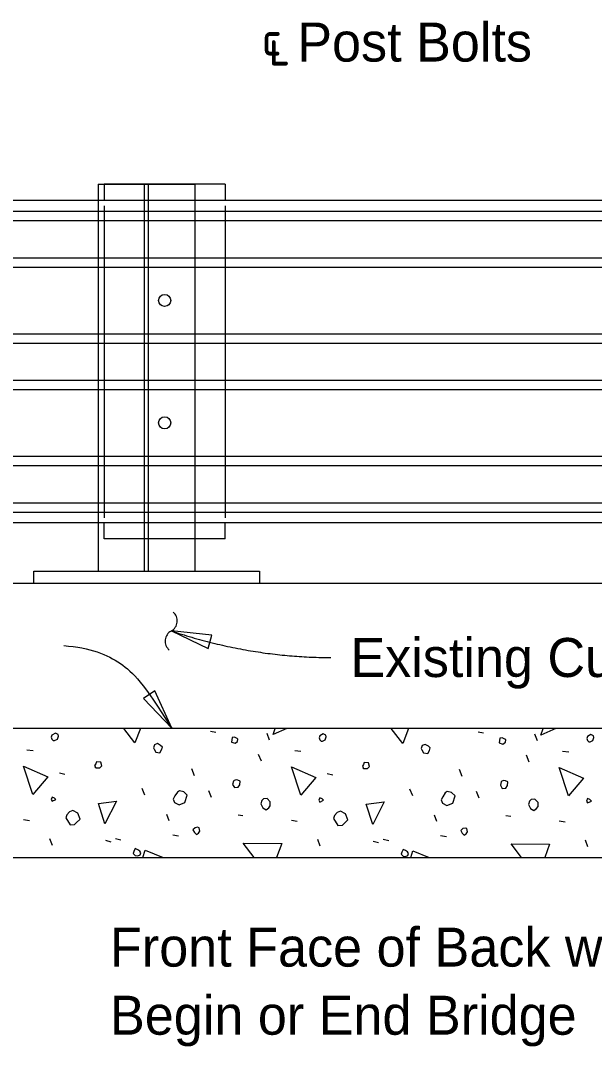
# Model space of a CAD drawing. Extents: x 21665 to 21741.5, y 56121.9 to 56164.2.
# Drawn here: x 21679.75 to 21682.72, y 56140.02 to 56145.33 of the extents above; entities that cross this region are included whole.
import ezdxf

# ---------------------------------------------------------------- set-up
doc = ezdxf.new("R2010")
doc.units = 0
for name, color, linetype in [('Dimension', 7, 'Continuous'), ('ExistSuperStruct', 7, 'Continuous'), ('Miscellaneous', 7, 'Continuous'), ('SteelMisc', 7, 'Continuous'), ('SteelMisc_h', 7, 'Continuous'), ('TextStructures', 7, 'Continuous')]:
    doc.layers.add(name, color=color, linetype=linetype)

msp = doc.modelspace()

# ---------------------------------------------------------------- linework, layer by layer
at = {"layer": 'Dimension'}
for points in [[(21680.5288, 56142.1727), (21680.7195, 56142.0819), (21680.7388, 56142.1497)], [(21680.5306, 56141.6698), (21680.4441, 56141.8625), (21680.3855, 56141.8233)]]:
    msp.add_lwpolyline(points, close=True, dxfattribs=at)
for centre, start, end in [((21680.4996, 56142.2244), 298.3371, 50.0643), ((21680.5562, 56142.1195), 118.3371, 230.0643)]:
    msp.add_arc(centre, 0.0596, start, end, dxfattribs=at)
for points, degree in [([(21680.528, 56142.1727), (21680.9408, 56142.035), (21681.3536, 56142.035)], 2), ([(21679.972, 56142.0966), (21680.1099, 56142.087), (21680.284, 56142.0123), (21680.3829, 56141.9034), (21680.5306, 56141.6698)], 3)]:
    msp.add_open_spline(points, degree=degree, dxfattribs=at)
at = {"layer": 'ExistSuperStruct'}
for p, q in [((21674.8449, 56142.4186), (21684.442, 56142.4186)), ((21684.5591, 56141.6686), (21674.8449, 56141.6686)), ((21674.8449, 56141.0019), (21684.5591, 56141.0019))]:
    msp.add_line(p, q, dxfattribs=at)
at = {"layer": 'Miscellaneous'}
for p, q in [((21680.8066, 56144.4811), (21680.1816, 56144.4811)), ((21680.1816, 56144.4811), (21680.1816, 56144.3977)), ((21680.8066, 56144.4811), (21680.8066, 56144.3977)), ((21680.1816, 56144.3692), (21680.1816, 56142.7573)), ((21680.8066, 56144.3692), (21680.8066, 56142.7573)), ((21680.1816, 56142.6477), (21680.1816, 56142.7311)), ((21680.8066, 56142.6477), (21680.8066, 56142.7311)), ((21680.8066, 56142.6477), (21680.1816, 56142.6477)), ((21680.7314, 56141.655), (21680.7579, 56141.6497)), ((21681.0366, 56141.6079), (21681.0242, 56141.6415)), ((21682.116, 56141.6515), (21682.1425, 56141.6462)), ((21682.4212, 56141.6044), (21682.4089, 56141.6379)), ((21679.7821, 56141.5578), (21679.8139, 56141.5542)), ((21680.9941, 56141.4983), (21680.98, 56141.5336)), ((21681.1667, 56141.5542), (21681.1986, 56141.5507)), ((21682.3788, 56141.4948), (21682.3647, 56141.5301)), ((21682.5514, 56141.5507), (21682.5832, 56141.5472)), ((21680.6483, 56141.4234), (21680.6341, 56141.4588)), ((21682.0329, 56141.4199), (21682.0188, 56141.4552)), ((21679.95, 56141.4393), (21679.9783, 56141.4323)), ((21681.3347, 56141.4358), (21681.363, 56141.4287)), ((21680.3919, 56141.3227), (21680.3778, 56141.358)), ((21681.7766, 56141.3191), (21681.7625, 56141.3545)), ((21680.736, 56141.3109), (21680.7219, 56141.3463)), ((21682.1207, 56141.3074), (21682.1066, 56141.3427)), ((21679.765, 56141.1978), (21679.7951, 56141.1925)), ((21680.5175, 56141.1901), (21680.5051, 56141.2237)), ((21680.8739, 56141.2225), (21680.8987, 56141.219)), ((21681.1497, 56141.1942), (21681.1797, 56141.1889)), ((21681.9021, 56141.1865), (21681.8898, 56141.2201)), ((21682.2586, 56141.219), (21682.2833, 56141.2154)), ((21682.5344, 56141.1907), (21682.5644, 56141.1854)), ((21679.9135, 56141.0634), (21679.9011, 56141.097)), ((21680.1875, 56141.0899), (21680.2158, 56141.0829)), ((21680.2399, 56141.0999), (21680.2682, 56141.0928)), ((21680.5363, 56141.1182), (21680.5663, 56141.1129)), ((21681.2982, 56141.0599), (21681.2858, 56141.0935)), ((21681.5722, 56141.0864), (21681.6005, 56141.0793)), ((21681.6246, 56141.0964), (21681.6529, 56141.0893)), ((21681.921, 56141.1147), (21681.951, 56141.1094)), ((21682.6829, 56141.0563), (21682.6705, 56141.0899))]:
    msp.add_line(p, q, dxfattribs=at)
for points in [[(21680.3407, 56141.5931), (21680.2833, 56141.6686)], [(21680.3689, 56141.6686), (21680.3407, 56141.5931)], [(21681.0554, 56141.6373), (21681.065, 56141.6686)], [(21681.125, 56141.6686), (21681.0554, 56141.6373)], [(21681.7254, 56141.5896), (21681.6653, 56141.6686)], [(21681.7549, 56141.6686), (21681.7254, 56141.5896)], [(21682.44, 56141.6338), (21682.4508, 56141.6686)], [(21682.5175, 56141.6686), (21682.44, 56141.6338)], [(21679.9182, 56141.6055), (21679.9253, 56141.6055), (21679.9394, 56141.6126), (21679.9447, 56141.6285), (21679.9429, 56141.6373), (21679.9288, 56141.6444), (21679.9111, 56141.6338), (21679.9076, 56141.6232), (21679.9111, 56141.6126), (21679.9182, 56141.6055)], [(21680.8392, 56141.5967), (21680.8586, 56141.5914), (21680.871, 56141.6002), (21680.8728, 56141.6126), (21680.8692, 56141.6161), (21680.8551, 56141.6232), (21680.8427, 56141.6214), (21680.841, 56141.609), (21680.8392, 56141.5967)], [(21681.3029, 56141.602), (21681.3099, 56141.602), (21681.3241, 56141.609), (21681.3294, 56141.6249), (21681.3276, 56141.6338), (21681.3135, 56141.6409), (21681.2958, 56141.6302), (21681.2923, 56141.6196), (21681.2958, 56141.609), (21681.3029, 56141.602)], [(21682.2239, 56141.5931), (21682.2433, 56141.5878), (21682.2557, 56141.5967), (21682.2575, 56141.609), (21682.2539, 56141.6126), (21682.2398, 56141.6196), (21682.2274, 56141.6179), (21682.2256, 56141.6055), (21682.2239, 56141.5931)], [(21682.6875, 56141.5984), (21682.6946, 56141.5984), (21682.7087, 56141.6055), (21682.7141, 56141.6214), (21682.7123, 56141.6302), (21682.6981, 56141.6373), (21682.6805, 56141.6267), (21682.6769, 56141.6161), (21682.6805, 56141.6055), (21682.6875, 56141.5984)], [(21680.4397, 56141.5613), (21680.4485, 56141.5454), (21680.4697, 56141.5419), (21680.4786, 56141.5578), (21680.4821, 56141.5719), (21680.4733, 56141.5807), (21680.4574, 56141.5896), (21680.4414, 56141.5843), (21680.4361, 56141.5684), (21680.4397, 56141.5613)], [(21681.8244, 56141.5578), (21681.8332, 56141.5419), (21681.8544, 56141.5383), (21681.8632, 56141.5542), (21681.8668, 56141.5684), (21681.8579, 56141.5772), (21681.842, 56141.5861), (21681.8261, 56141.5807), (21681.8208, 56141.5648), (21681.8244, 56141.5578)], [(21679.8127, 56141.3268), (21679.765, 56141.4735), (21679.8905, 56141.4187), (21679.8127, 56141.3268)], [(21680.1374, 56141.4641), (21680.1586, 56141.4641), (21680.1692, 56141.4747), (21680.1639, 56141.4941), (21680.1409, 56141.4959), (21680.1374, 56141.4853), (21680.1321, 56141.4764), (21680.1374, 56141.4641), (21680.1338, 56141.4676)], [(21681.1974, 56141.3233), (21681.1497, 56141.47), (21681.2752, 56141.4152), (21681.1974, 56141.3233)], [(21681.5221, 56141.4605), (21681.5433, 56141.4605), (21681.5539, 56141.4711), (21681.5486, 56141.4906), (21681.5256, 56141.4924), (21681.5221, 56141.4818), (21681.5168, 56141.4729), (21681.5221, 56141.4605), (21681.5185, 56141.4641)], [(21682.5821, 56141.3197), (21682.5344, 56141.4665), (21682.6599, 56141.4117), (21682.5821, 56141.3197)], [(21680.8456, 56141.3781), (21680.8545, 56141.3622), (21680.8739, 56141.3639), (21680.8828, 56141.3763), (21680.8845, 56141.3958), (21680.8722, 56141.4011), (21680.8633, 56141.4028), (21680.8527, 56141.3993), (21680.8492, 56141.3958), (21680.8456, 56141.3781)], [(21682.2303, 56141.3745), (21682.2391, 56141.3586), (21682.2586, 56141.3604), (21682.2674, 56141.3728), (21682.2692, 56141.3922), (21682.2568, 56141.3975), (21682.248, 56141.3993), (21682.2374, 56141.3958), (21682.2338, 56141.3922), (21682.2303, 56141.3745)], [(21679.9117, 56141.2915), (21679.9312, 56141.3003), (21679.9241, 56141.3074), (21679.9117, 56141.3127), (21679.9064, 56141.3003), (21679.9117, 56141.2915)], [(21680.5457, 56141.2855), (21680.5687, 56141.2732), (21680.5988, 56141.2855), (21680.6111, 56141.3227), (21680.5935, 56141.3403), (21680.5705, 56141.3456), (21680.5599, 56141.3386), (21680.5475, 56141.3191), (21680.5387, 56141.3032), (21680.5457, 56141.2855)], [(21680.9906, 56141.2791), (21681.0012, 56141.2579), (21681.0189, 56141.2473), (21681.033, 56141.2579), (21681.0401, 56141.2685), (21681.0401, 56141.2897), (21681.0242, 56141.3056), (21681.0047, 56141.3038), (21680.9959, 56141.295), (21680.9906, 56141.2791)], [(21681.2964, 56141.2879), (21681.3159, 56141.2968), (21681.3088, 56141.3038), (21681.2964, 56141.3091), (21681.2911, 56141.2968), (21681.2964, 56141.2879)], [(21681.9304, 56141.282), (21681.9534, 56141.2696), (21681.9834, 56141.282), (21681.9958, 56141.3191), (21681.9781, 56141.3368), (21681.9552, 56141.3421), (21681.9446, 56141.335), (21681.9322, 56141.3156), (21681.9233, 56141.2997), (21681.9304, 56141.282)], [(21682.3753, 56141.2755), (21682.3859, 56141.2543), (21682.4036, 56141.2437), (21682.4177, 56141.2543), (21682.4248, 56141.2649), (21682.4248, 56141.2862), (21682.4089, 56141.3021), (21682.3894, 56141.3003), (21682.3806, 56141.2915), (21682.3753, 56141.2755)], [(21682.6811, 56141.2844), (21682.7005, 56141.2932), (21682.6935, 56141.3003), (21682.6811, 56141.3056), (21682.6758, 56141.2932), (21682.6811, 56141.2844)], [(21679.9824, 56141.2066), (21680.0054, 56141.1695), (21680.0284, 56141.1713), (21680.0372, 56141.1801), (21680.0567, 56141.1995), (21680.0443, 56141.2296), (21680.0196, 56141.2437), (21680.0019, 56141.2367), (21679.9878, 56141.2225), (21679.9824, 56141.2066)], [(21680.1851, 56141.1759), (21680.1515, 56141.2802), (21680.2452, 56141.2926), (21680.1851, 56141.1759)], [(21681.5698, 56141.1724), (21681.5362, 56141.2767), (21681.6299, 56141.2891), (21681.5698, 56141.1724)], [(21681.3671, 56141.2031), (21681.3901, 56141.1659), (21681.4131, 56141.1677), (21681.4219, 56141.1766), (21681.4414, 56141.196), (21681.429, 56141.2261), (21681.4042, 56141.2402), (21681.3866, 56141.2331), (21681.3724, 56141.219), (21681.3671, 56141.2031)], [(21680.6476, 56141.1306), (21680.6583, 56141.12), (21680.6689, 56141.1271), (21680.6759, 56141.1377), (21680.6724, 56141.1553), (21680.6636, 56141.1571), (21680.6512, 56141.1553), (21680.6406, 56141.1447), (21680.6476, 56141.1306)], [(21682.0323, 56141.1271), (21682.0429, 56141.1165), (21682.0535, 56141.1235), (21682.0606, 56141.1341), (21682.0571, 56141.1518), (21682.0482, 56141.1536), (21682.0359, 56141.1518), (21682.0253, 56141.1412), (21682.0323, 56141.1271)], [(21680.3424, 56141.0115), (21680.3548, 56141.0098), (21680.3672, 56141.0151), (21680.3707, 56141.0257), (21680.3654, 56141.0345), (21680.3548, 56141.0416), (21680.3424, 56141.0469), (21680.3354, 56141.0327), (21680.3318, 56141.0221), (21680.3424, 56141.0115)], [(21680.3818, 56141.0019), (21680.3931, 56141.0387), (21680.4858, 56141.0019)], [(21680.9566, 56141.0019), (21680.9004, 56141.0758), (21681.1002, 56141.074), (21681.0732, 56141.0019)], [(21681.7271, 56141.008), (21681.7395, 56141.0062), (21681.7519, 56141.0115), (21681.7554, 56141.0221), (21681.7501, 56141.031), (21681.7395, 56141.038), (21681.7271, 56141.0433), (21681.7201, 56141.0292), (21681.7165, 56141.0186), (21681.7271, 56141.008)], [(21681.7675, 56141.0019), (21681.7778, 56141.0351), (21681.8616, 56141.0019)], [(21682.3386, 56141.0019), (21682.2851, 56141.0723), (21682.4849, 56141.0705), (21682.4592, 56141.0019)]]:
    msp.add_lwpolyline(points, dxfattribs=at)
at = {"layer": 'SteelMisc'}
for p, q in [((21680.1504, 56144.4811), (21680.6504, 56144.4811)), ((21680.1504, 56144.4811), (21680.1504, 56144.3977)), ((21680.6504, 56144.4811), (21680.6504, 56144.3977)), ((21683.1087, 56144.3977), (21674.8449, 56144.3977)), ((21674.8449, 56144.3422), (21683.1087, 56144.3422)), ((21674.8449, 56144.294), (21683.1087, 56144.294)), ((21674.8449, 56144.1012), (21683.1087, 56144.1012)), ((21674.8449, 56144.053), (21683.1087, 56144.053)), ((21674.8449, 56143.709), (21683.1087, 56143.709)), ((21674.8449, 56143.6608), (21683.1087, 56143.6608)), ((21674.8449, 56143.468), (21683.1087, 56143.468)), ((21674.8449, 56143.4198), (21683.1087, 56143.4198)), ((21674.8449, 56143.0759), (21683.1087, 56143.0759)), ((21674.8449, 56143.0276), (21683.1087, 56143.0276)), ((21674.8449, 56142.8348), (21683.1087, 56142.8348)), ((21674.8449, 56142.7866), (21683.1087, 56142.7866)), ((21683.1087, 56142.7311), (21674.8449, 56142.7311)), ((21680.1504, 56142.7311), (21680.1504, 56142.4811)), ((21680.6504, 56142.7311), (21680.6504, 56142.4811)), ((21679.817, 56142.4811), (21680.9837, 56142.4811)), ((21679.817, 56142.4186), (21679.817, 56142.4811)), ((21680.1504, 56142.4811), (21680.6504, 56142.4811)), ((21680.9837, 56142.4811), (21680.9837, 56142.4186)), ((21679.817, 56142.4186), (21680.9837, 56142.4186))]:
    msp.add_line(p, q, dxfattribs=at)
for centre in [(21680.4941, 56143.881), (21680.4941, 56143.2479)]:
    msp.add_circle(centre, 0.0312, dxfattribs=at)
at = {"layer": 'SteelMisc_h'}
for p, q in [((21680.39, 56142.4811), (21680.39, 56144.4811)), ((21680.4108, 56142.4811), (21680.4108, 56144.4811)), ((21680.1504, 56144.3977), (21680.1504, 56142.7311)), ((21680.6504, 56144.3977), (21680.6504, 56142.7311))]:
    msp.add_line(p, q, dxfattribs=at)

# ---------------------------------------------------------------- texts
at = {"layer": 'Dimension'}
for s, p in [('Front Face of Back wall &', (21680.2115, 56140.437)), ('Begin or End Bridge', (21680.2115, 56140.085))]:
    msp.add_text(s, height=0.2016, dxfattribs=at).set_placement(p)
at = {"layer": 'TextStructures'}
for s, p in [('℄ Post Bolts', (21680.9955, 56145.1156)), ('Existing Curb', (21681.4545, 56141.9342))]:
    msp.add_text(s, height=0.2016, dxfattribs=at).set_placement(p)

doc.saveas('drawing.dxf')
